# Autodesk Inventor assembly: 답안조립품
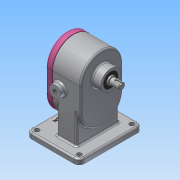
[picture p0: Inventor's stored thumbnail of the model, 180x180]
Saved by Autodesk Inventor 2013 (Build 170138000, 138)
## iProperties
Created: 2020-09
Part Number: 답안조립품
Document SubType Name: Assembly
Designer: Administrator
Author: Administrator
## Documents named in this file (11)
- C:\Users\Administrator\Desktop\700906V1050\답안조립품.iam
- C:\Users\Administrator\Desktop\700906V1050\본체.ipt
- C:\Users\Administrator\Desktop\700906V1050\볼트 M5.ipt
- C:\Users\Administrator\Desktop\700906V1050\커버.ipt
- C:\Users\Administrator\Desktop\700906V1050\베어링부시.ipt
- C:\Users\Administrator\Desktop\700906V1050\개스킷.ipt
- C:\Users\Administrator\Desktop\700906V1050\메인축.ipt
- C:\Users\Administrator\Desktop\700906V1050\스퍼기어.ipt
- C:\Users\Administrator\Desktop\700906V1050\오일 실 16 28 7.ipt
- C:\Users\Administrator\Desktop\700906V1050\키 6 x 6 x 18.ipt
- C:\Users\Administrator\Desktop\700906V1050\서브축.ipt
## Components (1 placed, 1 different names)
1. 개스킷:1
